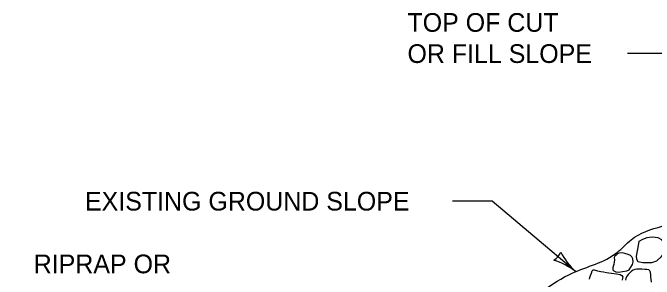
# Model space of a CAD drawing. Extents: x 49991.4 to 50021, y 49987.6 to 50011.4.
# Drawn here: x 50002.571 to 50004.632, y 49992.423 to 49993.278 of the extents above; entities that cross this region are included whole.
import ezdxf

# ---------------------------------------------------------------- set-up
doc = ezdxf.new("R2010")
doc.units = 0
for name, color, linetype in [('Level 1', 7, 'Continuous'), ('Level 2', 7, 'Continuous'), ('Level 3', 7, 'Continuous')]:
    doc.layers.add(name, color=color, linetype=linetype)

msp = doc.modelspace()

# ---------------------------------------------------------------- linework, layer by layer
at = {"layer": 'Level 1'}
for points in [[(50004.5832, 49992.5437), (50004.5784, 49992.5193), (50004.5739, 49992.4974), (50004.5754, 49992.4871), (50004.5798, 49992.4804), (50004.5956, 49992.4768), (50004.6247, 49992.4768), (50004.6409, 49992.4826), (50004.6562, 49992.496), (50004.666, 49992.5104), (50004.67, 49992.5251), (50004.667, 49992.5377), (50004.6572, 49992.5493), (50004.6448, 49992.5556), (50004.6256, 49992.5583), (50004.6089, 49992.5556), (50004.5946, 49992.5507)], [(50004.5184, 49992.5066), (50004.5138, 49992.5044), (50004.5096, 49992.5003), (50004.5061, 49992.4972), (50004.5034, 49992.4925), (50004.5044, 49992.4846), (50004.5039, 49992.479), (50004.5029, 49992.4699), (50004.499, 49992.4607), (50004.4992, 49992.4537), (50004.5029, 49992.4499), (50004.5093, 49992.4473), (50004.5187, 49992.4461), (50004.53, 49992.4477), (50004.5438, 49992.4495), (50004.5517, 49992.4535), (50004.5573, 49992.4614), (50004.5625, 49992.4701), (50004.5642, 49992.4788), (50004.564, 49992.4887), (50004.5608, 49992.4949), (50004.5559, 49992.4997), (50004.5487, 49992.5021), (50004.5379, 49992.5052), (50004.5288, 49992.5077)]]:
    msp.add_lwpolyline(points, close=True, dxfattribs=at)
for points in [[(50004.4246, 49992.4229), (50004.4251, 49992.4291), (50004.4278, 49992.4349), (50004.4303, 49992.4428), (50004.433, 49992.4504), (50004.4359, 49992.4529), (50004.4396, 49992.4533), (50004.4502, 49992.4502), (50004.4611, 49992.4479), (50004.4694, 49992.4466), (50004.4788, 49992.4452), (50004.4862, 49992.4439), (50004.495, 49992.443), (50004.511, 49992.4408), (50004.5234, 49992.4381), (50004.5278, 49992.4354), (50004.5312, 49992.4309), (50004.5307, 49992.4264), (50004.5295, 49992.4204)], [(50004.6236, 49992.4133), (50004.6226, 49992.4238), (50004.6219, 49992.4312), (50004.6214, 49992.4366), (50004.6204, 49992.4458), (50004.6182, 49992.4496), (50004.6148, 49992.4529), (50004.6089, 49992.4545), (50004.6017, 49992.4547), (50004.5926, 49992.4549), (50004.5835, 49992.4549), (50004.5766, 49992.4549), (50004.5702, 49992.4543), (50004.5645, 49992.4525), (50004.5594, 49992.4487), (50004.5535, 49992.4437), (50004.5485, 49992.4381), (50004.5446, 49992.4326), (50004.5409, 49992.4258), (50004.5402, 49992.4205)]]:
    msp.add_lwpolyline(points, dxfattribs=at)
msp.add_spline([(50002.2619, 49991.3557), (50002.3349, 49991.3922), (50002.4238, 49991.4367), (50002.5291, 49991.5121), (50002.6072, 49991.52), (50002.7666, 49991.6222), (50002.9299, 49991.6979), (50003.0239, 49991.7534), (50003.1684, 49991.8089), (50003.2652, 49991.8664), (50003.4173, 49991.9368), (50003.5346, 49992.0036), (50003.7319, 49992.1001), (50003.896, 49992.1823), (50004.0361, 49992.2633), (50004.183, 49992.3286), (50004.3686, 49992.4424), (50004.513, 49992.5091), (50004.5584, 49992.5497), (50004.7647, 49992.6283), (50004.8545, 49992.6869), (50004.9836, 49992.7492), (50005.0555, 49992.7804)], degree=3, dxfattribs=at)
at = {"layer": 'Level 3'}
for p, q in [((50004.7364, 49993.1475), (50004.546, 49993.1475)), ((50004.1119, 49992.6736), (50003.9843, 49992.6736)), ((50004.3789, 49992.448), (50004.1119, 49992.6736))]:
    msp.add_line(p, q, dxfattribs=at)
for centre, radius, start, end in [((50004.281, 49992.5308), 0.0548, 301.9353, 337.6577), ((50004.5293, 49992.6118), 0.2223, 207.2525, 227.436), ((50004.2375, 49992.2629), 0.233, 52.6238, 71.8736)]:
    msp.add_arc(centre, radius, start, end, dxfattribs=at)

# ---------------------------------------------------------------- texts
at = {"layer": 'Level 2'}
for s, p in [('TOP OF CUT', (50003.8392, 49993.2175)), ('OR FILL SLOPE', (50003.8392, 49993.1175)), ('EXISTING GROUND SLOPE', (50002.8026, 49992.6436)), ('RIPRAP OR', (50002.6379, 49992.4422))]:
    msp.add_text(s, height=0.06, dxfattribs=at).set_placement(p)

doc.saveas('drawing.dxf')
